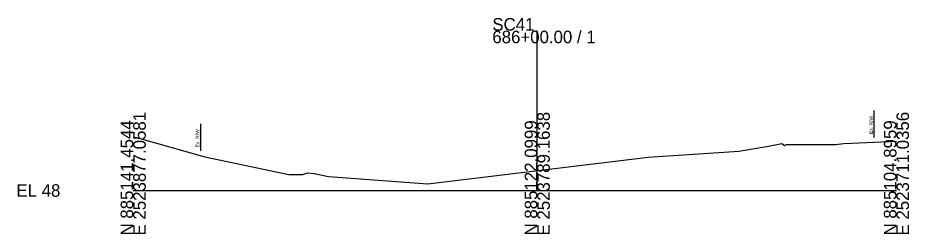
# Model space of a CAD drawing. Extents: x -26 to 183, y -10 to 24021.
# Drawn here: x -25.7 to 172.8, y 14990.3 to 15038.4 of the extents above; entities that cross this region are included whole.
import ezdxf

# ---------------------------------------------------------------- set-up
doc = ezdxf.new("R2010")
doc.units = 0
for name, color, linetype in [('RD_GPK_XS_Cell', 7, 'Continuous'), ('RD_XS_ExGround', 7, 'Continuous'), ('RD_XS_ExRW', 7, 'Continuous')]:
    doc.layers.add(name, color=color, linetype=linetype)

msp = doc.modelspace()

# ---------------------------------------------------------------- linework, layer by layer
at = {"layer": 'RD_GPK_XS_Cell'}
for p, q in [((90, 15000), (90, 15035.54)), ((0, 15000), (90, 15000)), ((90, 15000), (170, 15000))]:
    msp.add_line(p, q, dxfattribs=at)
at = {"layer": 'RD_XS_ExGround'}
for p, q in [((0, 15011.85), (0.74, 15011.82)), ((0.74, 15011.82), (15.97, 15007.52)), ((134.89, 15008.74), (141.53, 15009.84)), ((141.53, 15009.84), (144.48, 15010.43)), ((144.48, 15010.43), (145.1, 15009.99)), ((145.1, 15009.99), (145.49, 15010.25)), ((145.49, 15010.25), (147.51, 15010.25)), ((147.51, 15010.25), (156.41, 15010.26)), ((156.41, 15010.26), (158.28, 15010.46)), ((158.28, 15010.46), (170, 15011.01)), ((15.97, 15007.52), (34.65, 15003.58)), ((65.62, 15001.46), (114.73, 15007.4)), ((114.73, 15007.4), (134.89, 15008.74)), ((34.65, 15003.58), (37.79, 15003.59)), ((37.79, 15003.59), (38.89, 15003.9)), ((38.89, 15003.9), (40.32, 15003.8)), ((40.32, 15003.8), (43.54, 15003.1)), ((43.54, 15003.1), (65.62, 15001.46))]:
    msp.add_line(p, q, dxfattribs=at)
at = {"layer": 'RD_XS_ExRW'}
for p, q in [((165, 15017.77), (165, 15011.77)), ((15, 15014.79), (15, 15008.79))]:
    msp.add_line(p, q, dxfattribs=at)

# ---------------------------------------------------------------- texts
at = {"layer": 'RD_GPK_XS_Cell'}
for s, p in [('SC41', (80, 15035.54)), ('686+00.00 / 1', (80, 15032.74)), ('EL 48', (-26, 14998.6))]:
    msp.add_text(s, height=2.8, dxfattribs=at).set_placement(p)
for s, p in [('E 2523877.0581', (2.8, 14990)), ('E 2523789.1638', (92.8, 14990)), ('E 2523711.0356', (172.8, 14990)), ('N 885141.4544', (0, 14990)), ('N 885122.0999', (90, 14990)), ('N 885104.8959', (170, 14990))]:
    msp.add_text(s, height=2.8, rotation=90, dxfattribs=at).set_placement(p)
at = {"layer": 'RD_XS_ExRW'}
for p in [(164.75, 15012.56), (14.75, 15009.58)]:
    msp.add_text('Ex. R/W ', height=0.8, rotation=90, dxfattribs=at).set_placement(p)

doc.saveas('drawing.dxf')
